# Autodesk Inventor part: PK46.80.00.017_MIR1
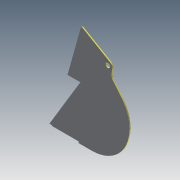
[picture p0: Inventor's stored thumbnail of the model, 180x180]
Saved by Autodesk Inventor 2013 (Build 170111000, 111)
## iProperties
Created: 2004-12
Part Number: PK46.80.00.017_MIR1
Material: Steel, Mild
Document SubType Name: Modeling
Designer: hoeyj
Manufacturer: Standard
Standards Organization: Custom
Density: 7.86 g/cm^3
Mass: 57972.3 g
Surface Area: 12737.7 cm^2
Volume: 7375.62 cm^3
Author: Salex
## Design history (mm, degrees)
derived "PK46.80.00.017.ipt"
  sketch "Sketch1"
    geometry: L1 (384.873, 16.042)-(239.873, 536.042) reference; L2 (239.873, 536.042)-(224.873, 566.042) reference; L3 (224.873, 566.042)-(-95.324, 379.229) reference; L4 (109.873, -588.958)-(259.873, -588.958) reference; L5 (589.873, -563.958)-(239.873, 16.042) reference; L6 (239.873, 16.042)-(384.873, 16.042) reference; L7 (-218.934, 105.321)-(-121.444, 224.362) reference; L8 (-110.587, 262.81)-(-119.667, 329.274) reference; L9 (589.873, -563.958)-(559.873, -563.958) reference; L10 (559.873, -563.958)-(559.873, -571.958) reference; L11 (559.873, -571.958)-(259.873, -571.958) reference; L12 (259.873, -571.958)-(259.873, -588.958) reference; L13 (239.873, 16.042)-(149.815, -38.304) reference; C1 r 25 at (-70.127, 336.042) reference; A1 r 425 centre (109.873, -163.958) between (-218.934, 105.321) and (109.873, -588.958) reference; A2 r 50 centre (-160.127, 256.042) between (-121.444, 224.362) and (-110.587, 262.81) reference; A3 r 50 centre (-70.127, 336.042) between (-95.324, 379.229) and (-119.667, 329.274) reference; 1 further point
body "Solid1"
tag "TaggingFeature3"
feature "DerivedBody::PK46.80.00.017.ipt" dims "d0" = 10
